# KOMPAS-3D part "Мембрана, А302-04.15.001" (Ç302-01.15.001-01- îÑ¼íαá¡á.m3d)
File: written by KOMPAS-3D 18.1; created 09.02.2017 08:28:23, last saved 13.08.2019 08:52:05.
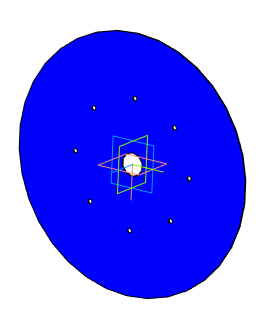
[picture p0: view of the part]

Document properties: Автор: Милов; Организация: Милов; Полное имя файла: D:\Мембранные насосы\Мембранный электропривод\А302-00.00.000 - ASTRA-302 (МЭ200)\3Д ПВХ\А302-01.15.001-01- Мембрана.m3d

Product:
- Part/product: Мембрана  | designation А302-04.15.001
    Материал: Фторопласт-4  ГОСТ 10007-80 Е (density 2200 kg/m3)
    Масса: 0.132112
    Раздел спецификации: Детали
    Форматы листов документа: A4
- Part/product: Мембрана  | designation А302-01.15.001-01
    Материал: Фторопласт-4  ГОСТ 10007-80 Е (density 2200 kg/m3)
    Масса: 0.132198
    Раздел спецификации: Детали
    Форматы листов документа: A4
    source file: А302-01.15.001 - Мембрана.cdw
- Part/product: Мембрана  | designation А302-02.15.001-01
    Материал: Фторопласт-4  ГОСТ 10007-80 Е (density 2200 kg/m3)
    Масса: 0.132198
    Раздел спецификации: Детали
    Форматы листов документа: A4

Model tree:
1. Эскиз:7
2. Операция выдавливания:12
     Расстояние 1 = 1; Расстояние 2 = 24.8832
3. Эскиз:8  (with: Операция выдавливания:12)
4. Вырезать элемент выдавливания:1
     Расстояние 1 = 0.1
5. Зеркальный массив:1
6. Экземпляр ( 1 )
7. Экземпляр ( 2 )  (with: Вырезать элемент выдавливания:1)
8. Эскиз:9  (with: Операция выдавливания:12)
9. Вырезать элемент выдавливания:2
     Расстояние 1 = 10
10. Массив по концентрической сетке:1  (with: Вырезать элемент выдавливания:2, Эскиз:9)  (labels: Фторопласт-4  ГОСТ 10007-80 Е)  (6 pattern instances)
     Шаг 2 = 360
11. Вырезать элемент выдавливания:2  (with: Эскиз:9)  (labels: Фторопласт-4  ГОСТ 10007-80 Е)  (1 pattern instances)
     N 1 = 1; Шаг 1 = 10; Шаг 2 = 360; Номер 1 = 1

Expressions: 250+28

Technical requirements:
  Gost Type A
